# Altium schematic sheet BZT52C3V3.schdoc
size 127 x 101 mm
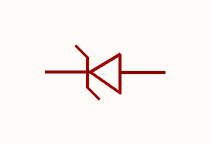
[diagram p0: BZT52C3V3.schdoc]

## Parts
D?  bzt52c3v3_c173413  [SOD-123_L2.7-W1.6-LS3.7-RD]  (value not drawn)

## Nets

Not connected (* = marked no-connect by the designer): D? 1(K) 2(A)

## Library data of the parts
D? = bzt52c3v3_c173413: 二极管配置:1个独立式;稳压值(标称值):3.3V;稳压值(范围):3.14V~3.47V;耗散功率(Pd):500mW;; Manufacturer: MDD(辰达半导体); AddInBom: yes; ModelId: ad7e39f9e5534b3c96ffdc5532ebb493; ModelName: SOD-123_L2.7-W1.6-H1.4-LS3.7; ModelTransform: 146.026,62.992,0,180,0,0,0.0005,0,0; Diode Configuration: 1个独立式; Zener Voltage(Nom): 3.3V; Reverse Leakage Current (Ir): 20uA@1V; Pd - Power Dissipation: 500mW; Impedance(Zzt): 130Ω; Tolerance: ±5%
